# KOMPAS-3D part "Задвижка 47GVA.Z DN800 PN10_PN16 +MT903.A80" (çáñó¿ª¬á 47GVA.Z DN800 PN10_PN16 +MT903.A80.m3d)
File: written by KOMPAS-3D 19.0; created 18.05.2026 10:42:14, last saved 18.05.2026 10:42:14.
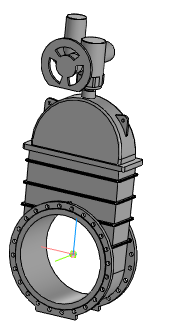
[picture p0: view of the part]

Document properties: Автор: Энергия; Полное имя файла: ..\Задвижка 47GVA.Z DN350_DN1200+MT903.A\Задвижка 47GVA.Z DN800 PN10_PN16 +MT903.A80.a3d

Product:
- Part/product: Задвижка 47GVA.Z DN800 PN10_PN16 +MT903.A80
    Масса: 2934.02
  - Body: Электропривод МТ903.А80 без блока управления
      Масса: 346.451
  - Body: Задвижка 47GVA.Z DN800 PN10_PN16 без исполнит. мех.
      Масса: 2587.56

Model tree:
1. Операция без истории:1
2. Операция без истории:2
